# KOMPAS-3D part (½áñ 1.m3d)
File: created 10.02.2016 11:24:24, last saved 22.07.2016 16:32:08.
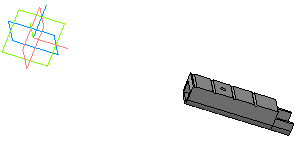
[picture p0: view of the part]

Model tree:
1. Эскиз:1
2. Операция выдавливания:1
     Расстояние 1 = 8
3. Эскиз:2
4. Операция выдавливания:2
     Расстояние 1 = 15.5
5. Вырезать элемент выдавливания:1
     Расстояние 1 = 320
6. Скругление:1
     Радиус = 7
7. Эскиз:3
8. Вырезать элемент выдавливания:2
     Расстояние 1 = 20
9. Эскиз:4
10. Вырезать элемент выдавливания:3
     Расстояние 2 = 40; Расстояние 1 = 65
11. Эскиз:5
12. Вырезать элемент выдавливания:4
     Расстояние 2 = 40; Расстояние 1 = 2
13. Эскиз:7
14. Вырезать элемент выдавливания:5
     Расстояние 1 = 40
